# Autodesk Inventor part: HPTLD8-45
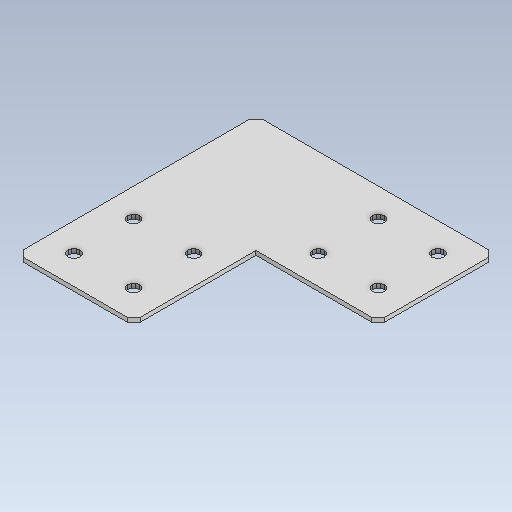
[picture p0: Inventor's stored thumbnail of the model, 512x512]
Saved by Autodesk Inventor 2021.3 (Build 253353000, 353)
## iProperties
Created: 2022-02
Part Number: HPTLD8-45
Material: 一般
Document SubType Name: Modeling
Designer: kengo
Density: 1 g/cm^3
Appearance: 既定
Author: kengo
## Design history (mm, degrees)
feature "HPTLD8-45"
node "ソリッド1"
